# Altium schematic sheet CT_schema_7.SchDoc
size 277 x 170 mm
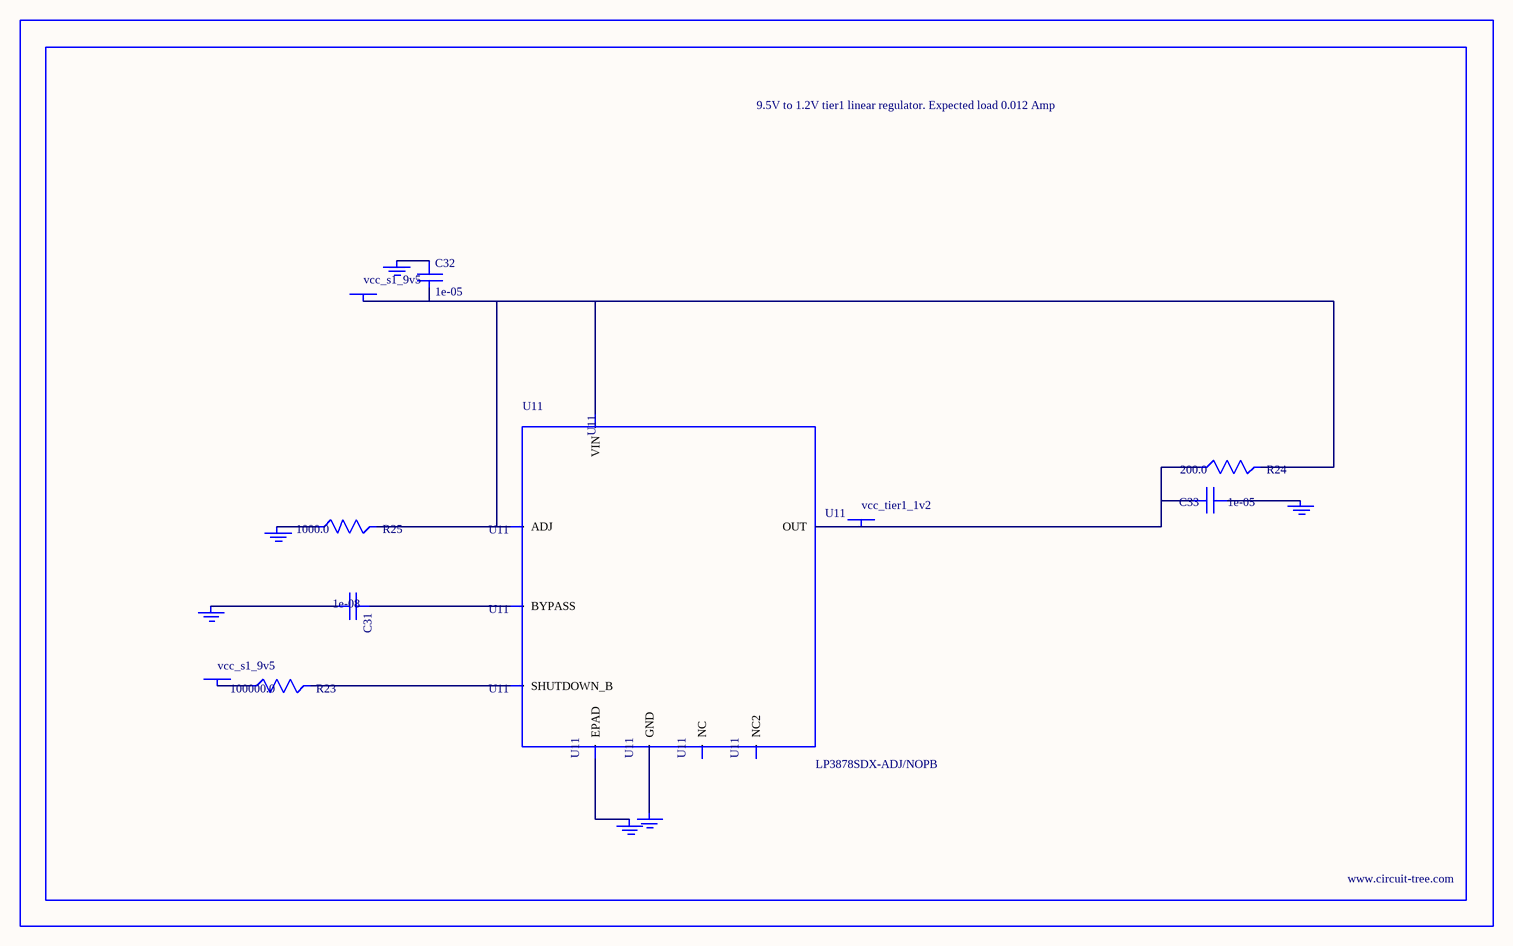
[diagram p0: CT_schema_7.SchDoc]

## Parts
BORDER6  (no value)
C31  1e-08  [C0402]
C32  1e-05  [C1206]
C33  1e-05  [C0805]
GND_INSTANCE_6_0  (no value)
GND_INSTANCE_6_1  (no value)
GND_INSTANCE_6_2  (no value)
GND_INSTANCE_6_3  (no value)
GND_INSTANCE_6_4  (no value)
GND_INSTANCE_6_5  (no value)
POWER_INSTANCE_6_0  vcc_s1_9v5
POWER_INSTANCE_6_1  vcc_s1_9v5
POWER_INSTANCE_6_2  vcc_tier1_1v2
R23  100000.0  [R0603]
R24  200.0  [R0603]
R25  1000.0  [R0603]
U11  LP3878SDX-ADJ/NOPB  [WSON-8]

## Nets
NetC31_1: C31.1 U11.1(BYPASS)
NetC31_2: C31.2 GND_INSTANCE_6_0.0(GND)
NetC32_1: C32.1 GND_INSTANCE_6_1.0(GND)
NetC32_2: C32.2 POWER_INSTANCE_6_0.0(PWR) R24.2 R25.2 U11.4(VIN) U11.6(ADJ)
NetC33_1: C33.1 GND_INSTANCE_6_2.0(GND)
NetC33_2: C33.2 POWER_INSTANCE_6_2.0(PWR) R24.1 U11.5(OUT)
NetGND_INSTANCE_6_3_0: GND_INSTANCE_6_3.0(GND) R25.1
NetGND_INSTANCE_6_4_0: GND_INSTANCE_6_4.0(GND) U11.PAD(EPAD)
NetGND_INSTANCE_6_5_0: GND_INSTANCE_6_5.0(GND) U11.3(GND)
NetPOWER_INSTANCE_6_1_0: POWER_INSTANCE_6_1.0(PWR) R23.1
NetR23_2: R23.2 U11.8(SHUTDOWN_B)

Not connected (* = marked no-connect by the designer): U11 2(NC) 7(NC2)

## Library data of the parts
BORDER6 = BORDER_PAGE6
C31 = C0402C103K3RAC
C32 = C1206C106K3RACTU
C33 = GRM219R60J106ME19D
GND_INSTANCE_6_0-GND_INSTANCE_6_5 = GND
POWER_INSTANCE_6_0-POWER_INSTANCE_6_2 = PWR
R23 = RC0603JR-07100KL
R24 = RC0603JR-07200RL
R25 = RC0603JR-071KL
